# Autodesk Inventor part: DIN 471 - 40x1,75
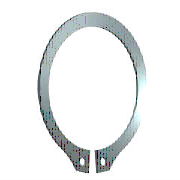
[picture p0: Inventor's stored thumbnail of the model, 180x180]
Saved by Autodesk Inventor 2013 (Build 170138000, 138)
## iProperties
Created: 2012-02
Part Number: DIN 471 - 40x1,75
Material: Stahl, weich
Description: Sicherungsringe für Wellen
Document SubType Name: Modeling
Standard: DIN 471
Designer: Dan
Standards Organization: DIN
Language: de-DE
Size Designation: 40x1,75
Categories: <MemberInstance><Categories><Category DisplayName="Wellenteile" InternalName="7f7aeb1f-a693-4053-b835-cee3144e0d98" Mnemonic="SHFT"><Category DisplayName="Siche
Density: 7.86 g/cm^3
IsCustomPart: 0
Author: Dan
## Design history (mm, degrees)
node "WorkPlane1"
workplane "Work Plane2"
node "WorkPlane2"
node "WorkPoint1"
node "WorkAxis1"
body "Solid1"
node "Skizze1"
sketch "Skizze2"
  geometry: L1 (6.25, -23.827)-(6.25, -19.841); L2 (1.25, -24.708)-(6.25, -23.827); L3 (1.25, -18.708)-(1.25, -24.708); L4 (-1.25, -18.708)-(-1.25, -24.708); L5 (-1.25, -24.708)-(-6.25, -23.827); L6 (-6.25, -23.827)-(-6.25, -19.841); A1 r 18.75 centre (0, 0) between (1.25, -18.708) and (-1.25, -18.708); A2 r 21.95 centre (0, 1.2) between (6.25, -19.841) and (-6.25, -19.841); 1 further point
  constraints: 12 end point, 4 point on circle, 4 vertical, 2 centre point
  dimensions: "d2" = 18.75 radius of A1 (= 0.5 x Diam2); "d4" = 21.95 radius of A2 (= 0.166667 x ParA + 0.5 x Diam2 + 0.5 x b); "d6" = 0 horizontal distance of A2.centre A1.centre; "d8" = 1.25 horizontal distance of L3.start A1.centre (= 0.5 x Diam5); "d10" = 1.25 horizontal distance of L4.start A1.centre (= 0.5 x Diam5); "d12" = 6 distance of L4.start L4.end (= ParA); "d14" = 6 distance of L3.start L2.start (= ParA); "d16" = 80 deg angle of L2 L3; "d18" = 80 deg angle of L4 L5; "d20" = 5 horizontal distance of L4.start L6.end (= 2 x Diam5); "d22" = 5 horizontal distance of L1.start L3.start (= 2 x Diam5); "d24" = 1.2 distance of A1.centre A2.centre (= -msp_r2 + 0.5 x Diam2 + b); "d52" = 0 distance of point (0, 0) A1.centre; "d53" = 0 distance of A1.centre point (0, 0)
extrude "Extrusion1" new body sketch "Skizze2" distance "d25" = 1.75 (= ParS); taper "d26" = 0 deg
sketch "Skizze3"
  geometry: L1 (-1.25, -18.708)-(-1.25, -24.708) reference; L2 (-1.25, -24.708)-(-6.25, -23.827) reference; 1 further point
  dimensions: "d30" = 2 distance from line of L1 point (-3.25, -21.614) (= 0.8 x Diam5); "d32" = 2.7 distance from line of L2 point (-3.25, -21.614) (= 0.45 x ParA)
hole "Bohrung1" sketch "Skizze3" diameter "d33" = 2.5 (= Diam5); stored, may be unused: countersink angle "d37" = 60 deg, drill point angle "d39" = 118 deg; dims "d34" = 6, "d35" = 4, "d36" = 2, "d38" = 8
sketch "Skizze4"
  geometry: L1 (1.25, -24.708)-(1.25, -18.708) reference; L2 (6.25, -23.827)-(1.25, -24.708) reference; 1 further point
  dimensions: "d41" = 2 distance from line of L1 point (3.25, -21.614) (= 0.8 x Diam5); "d43" = 2.7 distance from line of L2 point (3.25, -21.614) (= 0.45 x ParA)
hole "Bohrung2" sketch "Skizze4" diameter "d44" = 2.5 (= Diam5); stored, may be unused: countersink angle "d48" = 60 deg, drill point angle "d50" = 118 deg; dims "d45" = 6, "d46" = 4, "d47" = 2, "d49" = 8
fillet "Rundung1" dims "d51" = 3.75 (= 1.5 x Diam5)
other parameters: "Diam5" = 2.5 [user parameter; used in 9 equation terms], "ParA" = 6 [user parameter; used in 6 equation terms], "b" = 4.4 [user parameter; used in 3 equation terms], "ParS" = 1.75 [user parameter; used in 2 equation terms], "Diam2" = 37.5 [user parameter; used in 4 equation terms], "msp_r2" = 21.95 (= 0.166667 x ParA + 0.5 x Diam2 + 0.5 x b) [user parameter; used in 1 equation term], "d0" = -1.75 (computed from ParS), "d1" = 14.3 (derived), "d3" = 0, "d5" = 0 (derived), "d7" = 1 (derived), "d9" = 1 (derived), "d11" = 4.8 (derived), "d13" = 4.8 (derived), "d15" = 80 deg (derived), "d17" = 80 deg (derived), "d19" = 4 (derived), "d21" = 4 (derived), "d23" = 0.95 (derived), "d27" = 0, "d28" = 0, "d29" = 1.6 (derived), "d31" = 2.16 (derived), "d40" = 1.6 (derived), "d42" = 2.16 (derived), "d55" = 0, "d56" = 0, "d57" = 0, "d58" = 0, "TEMPLATE" = 12.345 [user parameter]
